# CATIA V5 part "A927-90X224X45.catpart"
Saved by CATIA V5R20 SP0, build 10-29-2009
Part number: A927-90X224X45
Source: Unknown
Property "A": "50.000"
Property "ARTICLENO": "A927-90X224X45"
Property "BOMINFO": "A927-90X224X45"
Property "CODE": "A927-90X224X45"
Property "CREATOR": "CADENAS GmbH"
Property "D": "18.000"
Property "D1": "26.000"
Property "F": "28.000"
Property "FORM": "A"
Property "L": "224.000"
Property "L1": "100.000"
Property "L2": "20.000"
Property "L3": "50.000"
Property "LINA": "A927-90X224X45"
Property "NB": "A927-90X224X45"
Property "NBSYN": "$CODE."
Property "NN": "A927"
Property "NT": "VDI 3387 Removable Die Heels, steel and self-lubricating"
Property "R": "25.000"
Property "S": "45.000"
Property "SUPPLIER": "CF"
Property "T": "21.000"
Property "W": "90.000"
Bounding box of the stored display mesh (mm): x -45 to 45, y 0 to 224, z -45 to 0
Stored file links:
  C:\Users\borellobunino\Desktop\3D X SITO CF\A927\GSB_OILLESS_G2290509022445\CATIAV5\A927-90X224X45.catpart
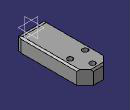
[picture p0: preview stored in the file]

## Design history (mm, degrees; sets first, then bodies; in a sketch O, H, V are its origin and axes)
Body1 "Geometry.1" (main body)
  Solid1 "A927-90X224X45.catpart": solid without history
